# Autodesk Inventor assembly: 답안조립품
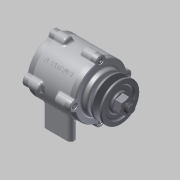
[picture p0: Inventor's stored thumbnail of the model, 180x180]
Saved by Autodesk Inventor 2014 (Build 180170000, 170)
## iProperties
Created: 2015-03
Part Number: 답안조립품
Document SubType Name: Assembly
Designer: MYHOME
Author: MYHOME
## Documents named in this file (11)
- C:\Documents and Settings\MYHOME\바탕 화면\450306V1025\답안조립품.iam
- C:\Documents and Settings\MYHOME\바탕 화면\450306V1025\본체.ipt
- C:\Documents and Settings\MYHOME\바탕 화면\450306V1025\커버.ipt
- C:\Documents and Settings\MYHOME\바탕 화면\450306V1025\커버2.ipt
- C:\Documents and Settings\MYHOME\바탕 화면\450306V1025\오일실.ipt
- C:\Documents and Settings\MYHOME\바탕 화면\450306V1025\M 4 x 12.ipt
- C:\Documents and Settings\MYHOME\바탕 화면\450306V1025\축.ipt
- C:\Documents and Settings\MYHOME\바탕 화면\450306V1025\베어링 6204.ipt
- C:\Documents and Settings\MYHOME\바탕 화면\450306V1025\키(4 x 4 x 12).ipt
- C:\Documents and Settings\MYHOME\바탕 화면\450306V1025\V벨트풀리.ipt
- C:\Documents and Settings\MYHOME\바탕 화면\450306V1025\너트 M12x1.25.ipt
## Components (14 placed, 6 different names)
1. KS B 2804 D D - 20 32 8:1
2. KS B 2023 6204 - 20 x 47 x 14:1 — 각도:1
3. KS B 2023 6204 - 20 x 47 x 14:2 — 각도:2
4. KS B 1311 (I) 4 x 4 x 12:1
5. 그루브 풀리1:1
6. KS B 1012 클래스 1 일반 - 미터 M12x1.25:1 — 각도:3
7. KS B 1003 - 미터 M 4 x 12:1
8. KS B 1003 - 미터 M 4 x 12:3
9. KS B 1003 - 미터 M 4 x 12:4
10. KS B 1003 - 미터 M 4 x 12:5
11. KS B 1003 - 미터 M 4 x 12:2
12. KS B 1003 - 미터 M 4 x 12:6
13. KS B 1003 - 미터 M 4 x 12:7
14. KS B 1003 - 미터 M 4 x 12:8
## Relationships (3: Angle 3)
- 각도:1 [Angle]: KS B 2023 6204 - 20 x 47 x 14:1
- 각도:2 [Angle]: KS B 2023 6204 - 20 x 47 x 14:2
- 각도:3 [Angle]: KS B 1012 클래스 1 일반 - 미터 M12x1.25:1
